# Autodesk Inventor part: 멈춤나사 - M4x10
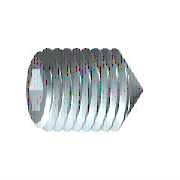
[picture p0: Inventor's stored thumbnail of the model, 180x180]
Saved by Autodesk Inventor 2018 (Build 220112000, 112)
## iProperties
Created: 2012-02
Part Number: 멈춤나사 - M4x10
Material: 강철, 연강
Description: 6각 소켓 머리 없는 멈춤 나사
Document SubType Name: Modeling
Standard: KS B 1028
Designer: mduedu
Standards Organization: KS
Language: ko-KR
Size Designation: 원추점 M4x10
Categories: <MemberInstance><Categories><Category DisplayName="조임쇠" InternalName="e4da775c-781d-43d5-af7c-5136215cf5a6" Mnemonic="FSTN"><Category DisplayName="볼트" InternalN
Density: 7.86 g/cm^3
Mass: 0.792069 g
Surface Area: 1.48192 cm^2
Volume: 0.100772 cm^3
Appearance: 강철
Author: mduedu
IsCustomPart: 1
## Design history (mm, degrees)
sketch "스케치1"
  geometry: L1 (0, 0)-(6.833, 0); L2 (10, 1.155)-(10, 2); L3 (10, 2)-(0, 2); L4 (10, 1.155)-(7.5, 1.155); L5 (7.5, 1.155)-(6.833, 0); L6 (0, -0.4)-(0, 2.4) reference; L7 (0, 2)-(0, 0)
  constraints: 13 end point, 3 parallel, 1 collinear, 1 perpendicular, 1 point on line
  dimensions: "d0" = 2.5 distance of L2.start L4.end (= INTI); "d1" = 60 deg angle of L5 L1; "d2" = 4 diameter of L3 L1 (= NND); "d3" = 2.3094 diameter of L4 L1 (= 1.1547 x SW); "d5" = 10 distance from line of L2 L3.end (= NLG)
revolve "본체" sketch "스케치1" stored, may be unused: angle "d6" = 90 deg
sketch "스케치2"
  geometry: L1 (-0.577, 1)-(0.577, 1); L2 (0.577, 1)-(1.155, 0); L3 (1.155, 0)-(0.577, -1); L4 (0.577, -1)-(-0.577, -1); L5 (-0.577, -1)-(-1.155, 0); L6 (-1.155, 0)-(-0.577, 1); 3 further points
  constraints: 12 end point, 1 coincident, 1 horizontal, 13 other
extrude "슬롯" join sketch "스케치2" taper "d7" = 0 deg; stored distance "d21" = 10
workaxis "Work Axis1"
workplane "Work Plane1"
sketch "스케치4"
  geometry: L1 (-5, 0.2)-(-3.2, 2) reference; L2 (-5, -0.2)-(-3.2, -2) reference; L3 (-3.2, 2)-(-5.2, 0); L4 (-3.2, -2)-(-5.2, 0); 2 further points
  constraints: 4 end point, 2 collinear, 1 coincident
body "Solid1"
feature "스레드" dims "d12" = 10 (= NLG), "d13" = 0
chamfer "모따기1" distance "d8" = 1.8 (computed from NND, SPD, FAWI); stored, may be unused: angle "d9" = 45 deg (= FAWI), second distance "d34" = 1.8 (computed from NND, SPD, FAWI)
chamfer "모따기2" distance "d10" = 0.42941 (= -0.5 x GD1 + 0.5 x NND); stored, may be unused: angle "d11" = 45 deg (= FAWI), second distance "d35" = 0.42941 (= -0.5 x GD1 + 0.5 x NND)
other parameters: "NND" = 4 [user parameter; used in 5 equation terms], "NLG" = 10 [user parameter; used in 2 equation terms], "INTI" = 2.5 [user parameter; used in 1 equation term], "FAWI" = 45 deg [user parameter; used in 4 equation terms], "SW" = 2 [user parameter; used in 2 equation terms], "GD1" = 3.14117 (= THREADDIA - 1.2269 x PTC) [user parameter; used in 2 equation terms], "d4" = 0, "FAWI1" = 45 deg [user parameter], "SPD" = 0.4 [user parameter; used in 2 equation terms], "d36" = 0, "d37" = 0, "GUL" = 0.42941 (= 0.61345 x PTC) [user parameter], "TPU" = 14.28571 (computed from PTC) [user parameter], "TOA" = 30 deg [user parameter], "THREADDIA" = 4 [user parameter; used in 1 equation term], "PTC" = 0.7 [user parameter; used in 4 equation terms], "GAL" = 0.42941 (= 0.61345 x PTC) [user parameter], "E0" = 2.31 (= 1.155 x SW) [user parameter]
